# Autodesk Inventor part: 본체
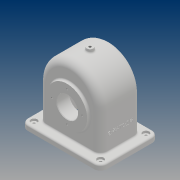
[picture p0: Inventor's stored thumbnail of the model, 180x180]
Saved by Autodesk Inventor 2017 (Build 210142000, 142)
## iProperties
Part Number: 본체
Material: 일반
Document SubType Name: Modeling
Designer: 20
Density: 1 g/cm^3
Appearance: 기본값
Author: 20
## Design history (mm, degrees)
sketch "스케치1"
  geometry: L1 (58, 0)-(58, -78); L2 (-58, 0)-(-58, -78); L3 (58, -78)-(-58, -78); A1 r 58 centre (0, 0) between (58, 0) and (-58, 0); 1 further point
  constraints: 6 end point, 2 point on circle, 2 tangent, 2 vertical, 1 centre point, 1 coincident, 1 horizontal
  dimensions: "d0" = 116 diameter of A1; "d1" = 78 distance from line of L3 point (0, 0)
extrude "돌출1" new body sketch "스케치1" stored distance "d2" = 77; taper "d3" = 0 deg
fillet "모깎기2" dims "d6" = 13
sketch "스케치4"
  geometry: L1 (-45, -78)-(45, -78) reference; C1 r 38 at (0, -13); 1 further point
  constraints: 1 centre point, 1 vertical alignment
  dimensions: "d11" = 76 diameter of C1; "d22" = 65 distance from line of L1 C1.centre
extrude "돌출3" join sketch "스케치4" distance "d13" = 5; taper "d14" = 0 deg
sketch "스케치6"
  geometry: L1 (120, 16.5)-(-30, 16.5); L2 (-30, 16.5)-(-30, -93.5); L3 (-30, -93.5)-(120, -93.5); L4 (120, -93.5)-(120, 16.5); L5 (120, 16.5)-(-30, -93.5); L6 (-30, 16.5)-(120, -93.5); L7 (90, -77)-(0, -77) reference; L8 (-13, -13)-(-13, -64) reference; L9 (0, 0)-(90, 0) reference; L10 (103, -13)-(103, -64) reference; A1 r 13 centre (90, -64) between (90, -77) and (103, -64) reference; A2 r 13 centre (0, -64) between (-13, -64) and (0, -77) reference; A3 r 13 centre (0, -13) between (0, 0) and (-13, -13) reference; A4 r 13 centre (90, -13) between (103, -13) and (90, 0) reference; 1 further point
  constraints: 12 end point, 2 midpoint, 2 parallel, 1 horizontal, 1 perpendicular
  dimensions: "d18" = 150 distance of L3.end L2.end; "d19" = 110 distance of L2.end L1.end
extrude "돌출5" join sketch "스케치6" distance "d20" = 10; taper "d21" = 0 deg
node "작업 평면1"
sketch "스케치9"
  geometry: C1 r 6 at (0, 0); 1 further point
  constraints: 1 centre point, 1 coincident
  dimensions: "d27" = 12 diameter of C1
extrude "돌출7" join sketch "스케치9" stored distance "d28" = 15; taper "d29" = 5 deg
sketch "스케치10"
  geometry: C1 r 38 at (0, 0) reference; C2 r 20 at (0, 0); 1 further point
  constraints: 1 centre point, 1 coincident
  dimensions: "d30" = 40 diameter of C2
extrude "돌출8" cut sketch "스케치10" stored distance "d31" = 15; taper "d32" = 0 deg
fillet "모깎기3" dims "d34" = 12
sketch "스케치13"
  geometry: C1 r 6 at (-108, 4.5); C2 r 6 at (18, 4.5); C3 r 6 at (18, -81.5); C4 r 6 at (-108, -81.5); A1 r 12 centre (-108, 4.5) between (-108, 16.5) and (-120, 4.5) reference; A2 r 12 centre (18, 4.5) between (30, 4.5) and (18, 16.5) reference; A3 r 12 centre (18, -81.5) between (18, -93.5) and (30, -81.5) reference; A4 r 12 centre (-108, -81.5) between (-120, -81.5) and (-108, -93.5) reference; 1 further point
  constraints: 4 centre point, 4 coincident
  dimensions: "d35" = 12 diameter of C1; "d36" = 12 diameter of C2; "d37" = 12 diameter of C3; "d38" = 12 diameter of C4
extrude "돌출9" cut sketch "스케치13" distance "d39" = 4; taper "d40" = 0 deg
sketch "스케치14"
  geometry: C1 r 6 at (0, 0) reference; C2 r 2.5 at (0, 0); C3 r 6 at (0, -86) reference; C4 r 2.5 at (0, -86); C5 r 6 at (-126, -86) reference; C6 r 2.5 at (-126, -86); C7 r 6 at (-126, 0) reference; C8 r 2.5 at (-126, 0); 1 further point
  constraints: 4 centre point, 4 coincident
  dimensions: "d41" = 5 diameter of C2; "d42" = 5 diameter of C4; "d43" = 5 diameter of C6; "d44" = 5 diameter of C8
extrude "돌출10" cut sketch "스케치14" distance "d45" = 20; taper "d46" = 0 deg
hole "구멍1" diameter "d49" = 4.459; stored, may be unused: countersink angle "d53" = 90 deg, drill point angle "d55" = 118 deg; dims "d47" = 10, "d48" = 10, "d50" = 10, "d51" = 4, "d52" = 2, "d54" = 15
sketch "스케치16"
  geometry: C1 r 20 at (0, 13) reference; C2 r 38 at (0, 13); 1 further point
  constraints: 1 centre point, 1 coincident
  dimensions: "d67" = 76 diameter of C2
extrude "돌출11" join sketch "스케치16" distance "d68" = 10; taper "d69" = 0 deg
sketch "스케치17"
  geometry: L1 (0, 51)-(0, 0) reference; L2 (78, 68.5)-(78, -17.5) reference; L3 (0, -13)-(68, -13) reference; 3 further points
  constraints: 1 midpoint, 1 other
  dimensions: "d70" = 40 distance from line of L2 point (38, 25.5); "d124" = 38.5 distance from line of L3 point (38, 25.5)
feature "엠보싱1" sketch "스케치17" dims "d0" = 116, "d1" = 78, "d71" = 0.5, "d72" = 0
fillet "모깎기4" dims "d73" = 3
fillet "모깎기5" dims "d74" = 3
fillet "모깎기6" dims "d75" = 3
chamfer "모따기1" distance "d76" = 1; stored, may be unused: second distance "d77" = 2, angle "d78" = 45 deg
fillet "모깎기7" dims "d79" = 3
sketch "스케치20"
  geometry: L1 (58, -65)-(58, 0) reference; L2 (-58, 0)-(-58, -65) reference; L3 (63, -78)-(-63, -78) reference; L4 (75, -78)-(63, -78) reference; L5 (-63, -78)-(-75, -78) reference; L6 (-52, -78)-(-52, 0); L7 (52, 0)-(52, -78); A1 r 58 centre (0, 0) between (58, 0) and (-58, 0) reference; A2 r 52 centre (0, 0) between (52, 0) and (-52, 0); 1 further point
  constraints: 4 end point, 2 point on circle, 2 point on line, 1 centre point, 2 other
  dimensions: "d91" = 6 radial gap between concentric circles of A1 A2
extrude "돌출12" cut sketch "스케치20" stored distance "d92" = 67; taper "d93" = 0 deg
fillet "모깎기8" dims "d94" = 8
sketch "스케치21"
  geometry: C1 r 20 at (0, 0) reference; C2 r 28 at (0, 0); 1 further point
  constraints: 1 centre point, 1 coincident
  dimensions: "d95" = 56 diameter of C2
extrude "돌출13" join sketch "스케치21" distance "d96" = 24; taper "d97" = 0 deg
feature "면 기울기2" dims angle "d98" = 40 deg
sketch "스케치22"
  geometry: C1 r 20 at (0, 0) reference; 2 further points
  constraints: 1 vertical alignment
  dimensions: "d99" = 29 distance of C1.centre point (0, 29)
hole "구멍4" sketch "스케치22" at (0, 29) diameter "d100" = 3.242; stored, may be unused: countersink angle "d104" = 90 deg, drill point angle "d106" = 118 deg; dims "d101" = 8, "d102" = 4, "d103" = 2, "d105" = 10
sketch "스케치23"
  geometry: C1 r 21 at (0, 0) reference; 2 further points
  constraints: 1 vertical alignment
  dimensions: "d110" = 29 distance of C1.centre point (0, -29)
hole "구멍5" sketch "스케치23" at (0, -29) diameter "d111" = 3.242; stored, may be unused: countersink angle "d115" = 90 deg, drill point angle "d117" = 118 deg; dims "d112" = 8, "d113" = 4, "d114" = 2, "d116" = 10
chamfer "모따기2" distance "d121" = 1; stored, may be unused: second distance "d122" = 2, angle "d123" = 45 deg
node "솔리드1"
pattern_circular "원형 패턴3" dims angle "d108" = 360 deg
pattern_circular "원형 패턴4" dims angle "d119" = 360 deg
other parameters: "d26" = 64
